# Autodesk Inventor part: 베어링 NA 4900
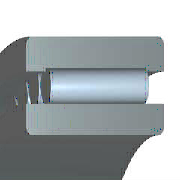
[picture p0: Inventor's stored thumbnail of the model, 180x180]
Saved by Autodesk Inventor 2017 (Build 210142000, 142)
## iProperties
Created: 2021-07
Part Number: 베어링 NA 4900
Material: 강철, 연강
Description: 니들 롤러 베어링 - 경계 치수 및 공차
Document SubType Name: Modeling
Standard: KS B 2029
Designer: mdu
Standards Organization: KS
Language: ko-KR
Size Designation: NA 4900 - 10 x 22 x 13
Categories: <MemberInstance><Categories><Category DisplayName="샤프트 부품" InternalName="7f7aeb1f-a693-4053-b835-cee3144e0d98" Mnemonic="SHFT"><Category DisplayName="베어링" Inter
Density: 7.86 g/cm^3
Mass: 23.8214 g
Surface Area: 38.613 cm^2
Volume: 3.03071 cm^3
Appearance: 베이지색
IsCustomPart: 0
Author: mdu
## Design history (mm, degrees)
sketch "스케치"
  geometry: L1 (1.857, 9)-(11.143, 9); L2 (11.143, 9)-(11.143, 7); L3 (13, 7)-(0, 7); L4 (1.857, 7)-(1.857, 9); L5 (1.857, 8)-(11.143, 8); L6 (6.5, 8)-(6.5, 7); L7 (0, 5)-(13, 5); L8 (0, 11)-(13, 11); L9 (13, 5)-(13, 7); L10 (13, 8.8)-(13, 11); L11 (1.857, 8.8)-(0, 8.8); L12 (11.143, 8.8)-(13, 8.8); L13 (-6, 0)-(36, 0) reference; L14 (0, -1.9)-(0, 14.9) reference
  constraints: 24 end point, 8 point on line, 3 midpoint, 3 parallel, 3 perpendicular, 2 symmetric about line, 1 horizontal, 1 other
  dimensions: "d6" = 10 diameter of L7 L13 (= WD); "d7" = 14 diameter of L3 L13 (= KID1); "d8" = 22 diameter of L8 L13 (= BD); "d9" = 16 diameter of L6.start L13 (= 0.5 x WD + 0.5 x BD); "d10" = 17.6 diameter of L12 L13 (= 0.9 x BD + 0.9 x WD - 0.8 x KID1); "d11" = 18 diameter of L1 L13 (= BD + WD - KID1); "d12" = 1.85714 distance between parallel lines of L14 L4 (= 0.142857 x KB); "d13" = 13 distance between parallel lines of L14 L9 (= KB); "d14" = 11.14286 distance between parallel lines of L14 L2 (= 0.857143 x KB)
revolve "본체" stored, may be unused: angle "d17" = 90 deg
revolve "롤러" stored, may be unused: angle "d18" = 90 deg
pattern_circular "IDS_ARRAYROLLER[SIMPL:T]" dims angle "d2" = 360 deg
body "Solid1"
fillet "모깎기1" dims "d0" = 0.3 (= KRS)
other parameters: "WD" = 10 [user parameter; used in 6 equation terms], "BD" = 22 [user parameter; used in 6 equation terms], "KB" = 13 [user parameter; used in 3 equation terms], "KID1" = 14 [user parameter; used in 4 equation terms], "KRS" = 0.3 [user parameter; used in 1 equation term], "d3" = 0, "d4" = 0, "d5" = 0, "d15" = 0, "d16" = 0, "BC0" = 9150000 [user parameter], "WR" = 5 (= 0.5 x WD) [user parameter], "BBA" = 0 [user parameter], "BC" = 8150000 [user parameter], "BR" = 11 (= 0.5 x BD) [user parameter]
